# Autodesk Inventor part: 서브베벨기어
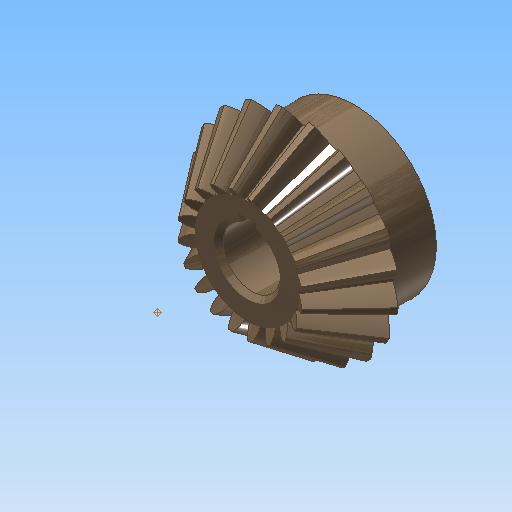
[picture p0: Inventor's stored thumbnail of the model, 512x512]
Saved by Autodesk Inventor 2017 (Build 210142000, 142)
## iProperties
Created: 2018-09
Part Number: 서브베벨기어
Material: 강철, 탄소
Document SubType Name: Modeling
Categories: <?xml version="1.0" encoding="UTF-16"?> <MemberInstance><Categories><FamilyTemplate><FamilyTemplateParameter ValueType="xs:double" Id="1" ObjectReferenceKey="da
Mass: 134.694 g
Surface Area: 63.6444 cm^2
Volume: 17.1585 cm^3
Density: 7.85 g/cm^3
Appearance: 얼룩무늬
CustomPartVersion: 1
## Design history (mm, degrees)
node "맨 위 점"
node "메쉬 평면2"
sketch "톱니 본체 스케치"
  geometry: L1 (0, 0)-(18.003, -31.331); L2 (18.003, -31.331)-(21.664, -28.891); L3 (21.664, -28.891)-(0, 0); L4 (20, -30)-(0, 0); L5 (10.813, -18.818)-(13.012, -17.352); L6 (18.003, -31.331)-(10.813, -18.818); L7 (21.664, -28.891)-(13.012, -17.352); L8 (0, -39.387)-(0, 6.564) reference; L9 (0, -30)-(21.664, -30)
  constraints: 16 end point, 4 point on line, 3 perpendicular, 2 collinear, 1 horizontal alignment, 1 vertical alignment
  dimensions: "d0" = 40 diameter of L4.start L8 (= da_de); "d1" = 36.00616 diameter of L1.end L8 (= da_dfe); "d2" = 43.3282 diameter of L2.end L8 (= da_dae); "d3" = 14.4 distance between parallel lines of L2 L5 (= da_b); "d4" = 28.8906 vertical distance of L2.end L1.start (= da_ve)
revolve "톱니 본체" sketch "톱니 본체 스케치" stored, may be unused: angle "d5" = 90 deg
node "시작점"
node "톱니 평면"
sketch "시작 스케치"
  geometry: L1 (0, -23.505)-(0, 10.645) reference; L2 (-0.834, -2.928)-(0.834, -2.928); A1 r 8.898 centre (-9.698, -3.713) between (-0.834, -2.928) and (-3.903, 3.04); A2 r 8.898 centre (9.698, -3.713) between (3.903, 3.04) and (0.834, -2.928); A3 r 27.357 centre (0, -24.037) between (3.903, 3.04) and (-3.903, 3.04); 1 further point
  constraints: 6 point on circle, 3 centre point, 3 symmetric about line, 2 end point, 1 coincident, 1 perpendicular, 1 other
  dimensions: "d7" = 8.89846 radius of A1 (= fd_rr); "d8" = 9.69794 horizontal distance of point (0, -24.037) A1.centre (= fd_x); "d9" = 20.32439 vertical distance of point (0, -24.037) A1.centre (= fd_y); "d57" = 27.35701 radius of A3 (= 0.5 x fd_dva + 0.3 x da_he); "d58" = 21.10901 distance from line of A3.centre L2 (= 0.5 x fd_dva - 1.12 x da_he)
node "끝점"
  node "끝 평면"
sketch "3D 스케치 오른쪽"
  node "Helical Curve Right" dims "d65" = 229.90621 (computed from da_dm, da_delta, da_beta), "d66" = 31.5, "d67" = 40 (= da_de), "d68" = -5.88003 (= -da_delta), "d69" = 12.16458 (computed from fd_loft, da_delta)
node "끝 평면 오른쪽"
sketch "끝 스케치 오른쪽"
  geometry: L1 (0, -22.649)-(0, 12.15) reference; L2 (-0.497, -1.72)-(0.497, -1.72); A1 r 5.299 centre (-5.775, -2.187) between (-0.497, -1.72) and (-2.324, 1.834); A2 r 5.299 centre (5.775, -2.187) between (2.324, 1.834) and (0.497, -1.72); A3 r 16.291 centre (0, -14.29) between (2.324, 1.834) and (-2.324, 1.834); 1 further point
  constraints: 6 point on circle, 3 centre point, 3 symmetric about line, 2 end point, 1 coincident, 1 perpendicular, 1 other
  dimensions: "d70" = 5.77526 horizontal distance of A3.centre A1.centre (computed from fd_x, fd_ratio); "d71" = 12.10346 vertical distance of point (0, -14.29) A1.centre (computed from fd_y, fd_ratio); "d72" = 5.29916 radius of A1 (computed from fd_rr, fd_ratio); "d73" = 12.57071 distance from line of point (0, -14.29) L2 (computed from d58, fd_ratio); "d74" = 16.29149 radius of A3 (computed from d57, fd_ratio)
feature "로프트 오른쪽" sketch "끝 스케치 오른쪽" dims "d75" = 0, "d77" = 0, "d79" = 0, "d80" = 90 deg, "d85" = 20, "d92" = 90 deg, "d93" = 90 deg, "da_teethtype" = 0 [user parameter]
sketch "3D 스케치 왼쪽"
  node "Helical Curve Left" dims "d26" = 229.90621 (computed from da_dm, da_delta, da_beta), "d27" = 12.16458 (computed from fd_loft, da_delta), "d28" = 40 (= da_de), "d29" = -5.88003 (= -da_delta)
node "끝 평면 왼쪽"
sketch "끝 스케치 왼쪽" dims "d56" = 10.82768 (derived)
  geometry: L1 (0, -35.087)-(0, 18.089) reference; L2 (-0.497, -1.716)-(0.497, -1.716); A1 r 5.299 centre (-5.775, -2.183) between (-0.497, -1.716) and (-2.324, 1.838); A2 r 5.299 centre (5.775, -2.183) between (2.324, 1.838) and (0.497, -1.716); A3 r 16.291 centre (0, -14.287) between (2.324, 1.838) and (-2.324, 1.838); 2 further points; 1 other entity
  constraints: 6 point on circle, 3 centre point, 3 symmetric about line, 2 end point, 1 coincident, 2 other
  dimensions: "d30" = 5.29916 radius of A1 (computed from fd_rr, fd_ratio); "d31" = 5.77526 horizontal distance of point (0, -14.287) A1.centre (computed from fd_x, fd_ratio); "d32" = 12.10346 vertical distance of A1.centre point (0, -14.287) (computed from fd_y, fd_ratio); "d61" = 16.29149 radius of A3 (computed from d57, fd_ratio); "d62" = 12.57071 distance from line of point (0, -14.287) L2 (computed from d58, fd_ratio)
feature "로프트 왼쪽" sketch "끝 스케치 왼쪽" dims "d35" = 0, "d37" = 0, "d39" = 0, "d40" = 90 deg, "d84" = 10, "d90" = 90 deg, "d91" = 90 deg, "da_teethtype" = 0 [user parameter]
sketch "본체 스케치"
  geometry: L1 (0, -35.038)-(0, -19.531) reference; L2 (18.003, -31.331)-(10.813, -18.818) reference; L3 (10.813, -18.818)-(0, -18.818); L4 (18.003, -31.331)-(0, -31.331)
  constraints: 4 end point, 2 perpendicular, 2 point on line
revolve "본체 고정" sketch "본체 스케치" stored, may be unused: angle "d46" = 90 deg
feature "피치 지름" dims angle "d47" = 90 deg
sketch "스케치8"
  geometry: C1 r 17 at (0, 0); 1 further point
  constraints: 1 centre point, 1 coincident
  dimensions: "d94" = 34 diameter of C1
extrude "돌출1" join sketch "스케치8" distance "d95" = 10; taper "d96" = 0 deg
sketch "스케치9"
  geometry: 1 further point
hole "구멍1" sketch "스케치9" at (0, 0) diameter "d97" = 12; stored, may be unused: countersink angle "d101" = 90 deg, drill point angle "d103" = 118 deg; dims "d98" = 6, "d99" = 4, "d100" = 2, "d102" = 8
sketch "스케치10"
  geometry: 1 further point
sketch "스케치11"
  geometry: 1 further point
sketch "스케치12"
  geometry: L1 (-2, 5.657)-(-2, 7.8); L2 (-2, 7.8)-(2, 7.8); L3 (2, 7.8)-(2, 5.657); A1 r 6 centre (0, 0) between (-2, 5.657) and (2, 5.657) reference; 1 further point
  constraints: 6 end point, 2 parallel, 2 point on circle, 1 perpendicular, 1 vertical
  dimensions: "d104" = 4 distance of L1.end L2.end; "d105" = 13.8 dimension on A1 L2
extrude "돌출2" cut sketch "스케치12" stored distance "d106" = 7; taper "d107" = 0 deg
chamfer "모따기1" distance "d108" = 1; stored, may be unused: second distance "d109" = 2, angle "d110" = 45 deg
body "Solid1"
feature "로프트" dims "d17" = 0, "d18" = 90 deg, "d19" = 0, "d20" = 90 deg, "d89" = 0, "da_teethtype" = 0 [user parameter]
pattern_circular "원형 패턴" dims angle "d22" = 360 deg, "d88" = 0, "da_teethtype" = 0 [user parameter]
pattern_circular "원형 패턴 오른쪽" dims angle "d82" = 360 deg, "da_teethtype" = 0 [user parameter]
pattern_circular "원형 패턴 왼쪽" dims angle "d42" = 360 deg, "da_teethtype" = 0 [user parameter]
sketch "끝 스케치"
  geometry: L1 (0, -15.359)-(0, 6.983) reference; L2 (-0.497, -1.72)-(0.497, -1.72); A1 r 5.299 centre (-5.775, -2.187) between (-0.497, -1.72) and (-2.324, 1.834); A2 r 5.299 centre (5.775, -2.187) between (2.324, 1.834) and (0.497, -1.72); A3 r 16.291 centre (0, -14.29) between (2.324, 1.834) and (-2.324, 1.834); 1 further point
  constraints: 6 point on circle, 3 centre point, 3 symmetric about line, 2 end point, 1 coincident, 1 other
  dimensions: "d12" = 5.29916 radius of A1 (computed from fd_rr, fd_ratio); "d15" = 5.77526 horizontal distance of A1.centre point (0, -14.29) (computed from fd_x, fd_ratio); "d16" = 12.10346 vertical distance of A1.centre point (0, -14.29) (computed from fd_y, fd_ratio); "d59" = 16.29149 radius of A3 (computed from d57, fd_ratio); "d60" = 12.57071 distance from line of A3.centre L2 (computed from d58, fd_ratio)
sketch "Sketch6"
  geometry: L1 (20, -30)-(0, 0) reference; L2 (0, -37.8)-(0, 6.3) reference
body "Srf1"
other parameters: "da_b" = 14.4 [user parameter; used in 2 equation terms], "da_de" = 40 [user parameter; used in 4 equation terms], "da_dae" = 43.3282 [user parameter; used in 2 equation terms], "da_dfe" = 36.00616 [user parameter; used in 1 equation term], "da_le" = 36.05551 [user parameter; used in 1 equation term], "da_omega" = 90 deg [user parameter; used in 1 equation term], "da_beta" = 0 [user parameter; used in 2 equation terms], "da_delta" = 5.88003 [user parameter; used in 8 equation terms], "da_alpha" = 20 deg [user parameter; used in 2 equation terms], "da_he" = 4.4 [user parameter; used in 4 equation terms], "da_ve" = 28.8906 [user parameter; used in 1 equation term], "fd_dv" = 48.07402 (computed from da_de, da_delta) [user parameter; used in 1 equation term], "fd_dva" = 52.07402 (computed from da_dae, da_delta) [user parameter; used in 3 equation terms], "fd_dvb" = 45.1748 (computed from fd_dv, da_alpha) [user parameter; used in 2 equation terms], "da_zv" = 240.37008 [user parameter; used in 1 equation term], "fd_loft" = 14.62 (= da_b + 0.05 x da_he) [user parameter; used in 4 equation terms], "fd_ratio" = 5.95514 (computed from da_le, fd_loft) [user parameter; used in 15 equation terms], "fd_rr" = 8.89846 (computed from fd_dd, fd_dvb) [user parameter; used in 6 equation terms], "fd_angle" = 0.66075 (computed from da_zv) [user parameter; used in 4 equation terms], "fd_x1" = 1.58709 (computed from da_dvw, fd_angle) [user parameter; used in 1 equation term], "fd_y1" = 23.98456 (computed from da_dvw, fd_angle) [user parameter; used in 1 equation term], "fd_x2" = 8.11084 (computed from fd_rr, fd_angle2, fd_angle) [user parameter; used in 1 equation term], "fd_y2" = 3.66016 (computed from fd_rr, fd_angle2, fd_angle) [user parameter; used in 1 equation term], "fd_x" = 9.69794 (= fd_x1 + fd_x2) [user parameter; used in 4 equation terms], "fd_y" = 20.32439 (= fd_y1 - fd_y2) [user parameter; used in 4 equation terms], "fd_angle2" = 3.57832 (computed from fd_dvb, fd_dd, da_alpha) [user parameter; used in 2 equation terms], "fd_dd" = 48.55402 (= fd_dva - 0.8 x da_he) [user parameter; used in 2 equation terms], "da_dvw" = 48.07402 [user parameter; used in 2 equation terms], "d11" = 14.62 (= fd_loft), "da_dm" = 32.01232 [user parameter; used in 2 equation terms], "da_x" = 0 [user parameter], "da_m" = 2 [user parameter], "d48" = 0, "d49" = 0, "d50" = 90 deg (= da_omega), "d51" = 9 deg (computed from da_z), "d52" = 0, "d53" = 0, "d54" = 0
